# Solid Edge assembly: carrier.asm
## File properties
Title: Carrier Assembly
Subject: Trolley Wheel Assembly
Author: edge
Keywords: Subassembly
Comments: Carrier Subassembly
Template: metric.asm
Last saved by: edge
Revision: 41
Application: Solid Edge
File Size: 0
Number of Sheets: 0
Number of Objects: 0
Username: edge
文書内容のタイプ: 1
Document Number: CSA-101
Revision: 1
Project Name: Trolley Wheel Assembly
Category: Subassembly
Manager: Brian Little
Company: Wheels R Us
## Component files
chead.par
Splate.par
mtgpin.par
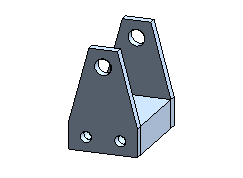
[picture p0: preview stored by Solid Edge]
